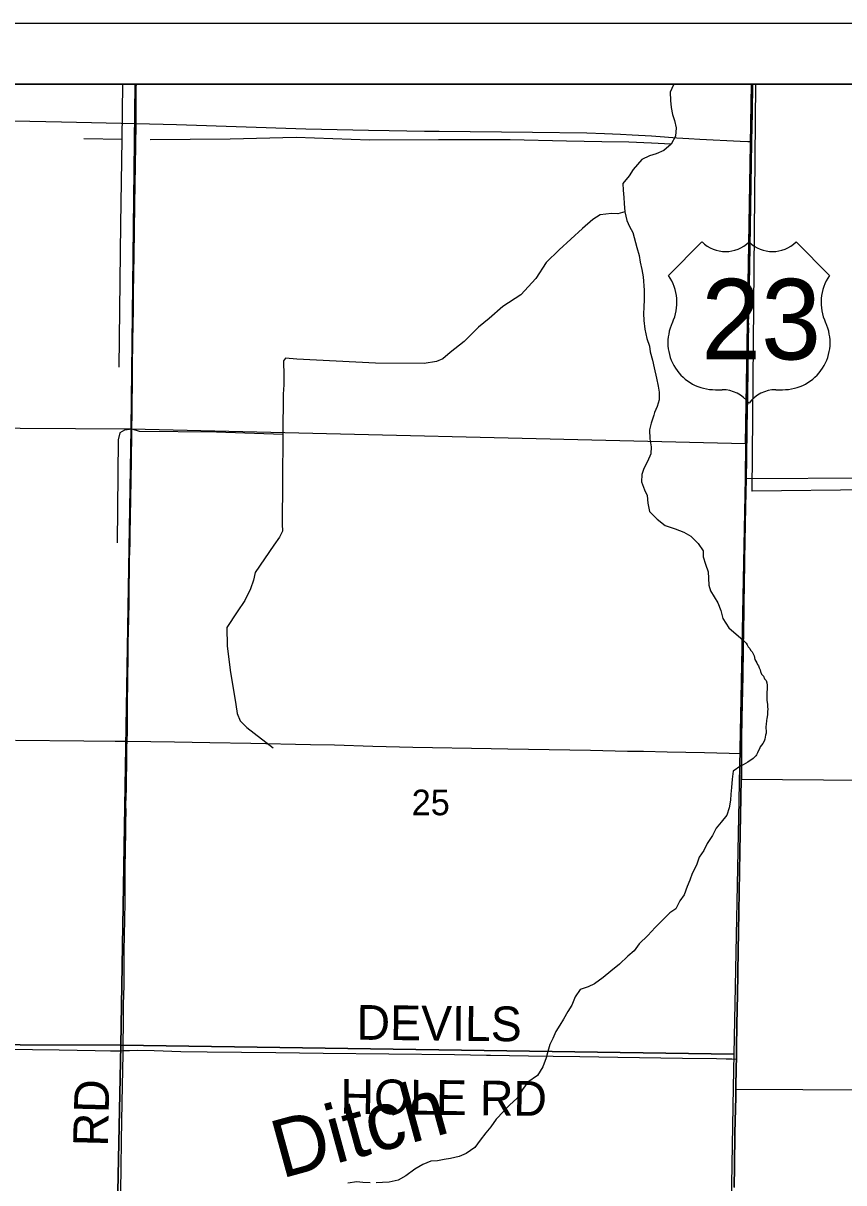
# Model space of a CAD drawing. Extents: x -8.3 to 42.1, y 0 to 22.
# Drawn here: x 6.765 to 8.107, y 19.103 to 21 of the extents above; entities that cross this region are included whole.
import ezdxf

# ---------------------------------------------------------------- set-up
doc = ezdxf.new("R2010")
doc.units = 0
for name, color, linetype in [('Default', 7, 'Continuous'), ('GM_X_Minor_River', 7, 'Continuous'), ('GM_X_Minor_River_Text', 7, 'Continuous'), ('GM_X_Section', 7, 'Continuous'), ('GM_X_Section_Text', 7, 'Continuous'), ('GM_X_State_Route', 7, 'Continuous'), ('GM_X_Township_Road', 7, 'Continuous'), ('GM_X_Township_Road_Text', 7, 'Continuous'), ('GM_X_US_Location', 7, 'Continuous'), ('GM_X_US_Route', 7, 'Continuous'), ('GM_X_US_Shield', 7, 'Continuous'), ('SH_Cut_Line', 7, 'Continuous'), ('SH_Data', 7, 'Continuous')]:
    doc.layers.add(name, color=color, linetype=linetype)

msp = doc.modelspace()

# ---------------------------------------------------------------- linework, layer by layer
at = {"layer": 'Default'}
for points in [[(6.9477, 20.9), (5.9435, 20.9), (5.9413, 20.342), (6.941, 20.3362)], [(7.9556, 20.9), (6.9477, 20.9), (6.941, 20.3362), (7.9462, 20.3122)]]:
    msp.add_lwpolyline(points, close=True, dxfattribs=at)
at = {"layer": 'GM_X_Minor_River'}
for p, q in [((7.9567, 20.2345), (7.9627, 20.9)), ((7.9566, 20.2348), (7.9567, 20.2348)), ((8.3532, 20.238), (7.9567, 20.2345))]:
    msp.add_line(p, q, dxfattribs=at)
for points in [[(6.9217, 20.4373), (6.9245, 20.6714), (6.9264, 20.8095), (6.9278, 20.9)], [(7.8289, 20.9), (7.8284, 20.8992), (7.8228, 20.8872), (7.8232, 20.8735), (7.8245, 20.8621), (7.8265, 20.8507), (7.83, 20.8407), (7.8327, 20.8289), (7.8316, 20.8152), (7.8245, 20.8021), (7.8125, 20.7918), (7.7999, 20.786), (7.7888, 20.7829), (7.7765, 20.7771), (7.7625, 20.7607), (7.7558, 20.7503), (7.7456, 20.7376), (7.7458, 20.727), (7.747, 20.7148), (7.7475, 20.7049), (7.7487, 20.6912), (7.7517, 20.6771), (7.7564, 20.6675), (7.7615, 20.6575), (7.7684, 20.6327), (7.7719, 20.6197), (7.7739, 20.609), (7.7766, 20.5972), (7.7786, 20.585), (7.7803, 20.563), (7.7803, 20.5485), (7.7796, 20.5349), (7.779, 20.525), (7.7795, 20.5133), (7.7814, 20.4992), (7.7848, 20.4843), (7.7887, 20.4717), (7.7903, 20.4622), (7.7938, 20.4484), (7.7968, 20.4358), (7.8006, 20.419), (7.8029, 20.4061), (7.8046, 20.3965), (7.8046, 20.3836), (7.8013, 20.3727), (7.7969, 20.3629)], [(6.9264, 20.8095), (6.8636, 20.811)], [(7.8245, 20.8021), (7.792, 20.8037), (7.7549, 20.8053), (7.711, 20.806), (7.6531, 20.8067), (7.5611, 20.8089), (7.4437, 20.8091), (7.3312, 20.8088), (7.2113, 20.8128), (7.1033, 20.8101), (6.9722, 20.8094)], [(7.7487, 20.6912), (7.7372, 20.6881), (7.7266, 20.6887), (7.7084, 20.6865), (7.6961, 20.6789), (7.6791, 20.6641), (7.6411, 20.6293), (7.6197, 20.6082), (7.6028, 20.5821), (7.5787, 20.5557), (7.549, 20.5367), (7.5266, 20.5168), (7.5092, 20.5024), (7.4859, 20.4794), (7.4627, 20.461), (7.4507, 20.4507), (7.4404, 20.4467), (7.4202, 20.4434), (7.3407, 20.4438), (7.2121, 20.45), (7.1936, 20.452), (7.1905, 20.4475), (7.191, 20.4228), (7.1906, 20.408), (7.1899, 20.3932), (7.1894, 20.3268), (7.1886, 20.2506), (7.1884, 20.18), (7.1885, 20.1686), (7.1837, 20.1588), (7.1743, 20.1458), (7.144, 20.101), (7.141, 20.0889), (7.1361, 20.0742), (7.127, 20.0555), (7.1144, 20.0368), (7.0978, 20.011), (7.0982, 19.981), (7.1033, 19.9414), (7.1121, 19.8854), (7.1144, 19.8702), (7.1194, 19.8583), (7.1301, 19.8474), (7.1732, 19.8145)], [(7.7969, 20.3629), (7.7961, 20.3588), (7.7916, 20.3456), (7.789, 20.3347), (7.7894, 20.3199), (7.7918, 20.3069), (7.7911, 20.2952), (7.7859, 20.2828), (7.7795, 20.2715), (7.7762, 20.2617), (7.7759, 20.2496), (7.7809, 20.2366), (7.7852, 20.227), (7.7864, 20.2144), (7.7891, 20.2011), (7.8013, 20.1883), (7.8147, 20.1781), (7.8308, 20.1724), (7.8451, 20.1671), (7.8567, 20.1604)], [(7.1894, 20.3268), (7.0808, 20.3306), (6.9547, 20.3321), (6.9427, 20.3358), (6.9301, 20.3343), (6.9228, 20.3295), (6.9199, 20.3182), (6.918, 20.1497)], [(7.8567, 20.1604), (7.8685, 20.1487), (7.8765, 20.1367), (7.877, 20.1269), (7.8805, 20.115), (7.8851, 20.1024), (7.8856, 20.0917), (7.8861, 20.0807), (7.8885, 20.0712), (7.8947, 20.0611), (7.9009, 20.0515), (7.9055, 20.0389), (7.909, 20.0259), (7.9185, 20.0109), (7.9421, 19.9902)], [(7.9421, 19.9902), (7.9473, 19.9853), (7.9487, 19.9826), (7.9506, 19.9796), (7.9528, 19.9769), (7.9543, 19.9742), (7.9569, 19.9715), (7.9587, 19.9681), (7.9602, 19.965), (7.9612, 19.9589), (7.9646, 19.9536), (7.9657, 19.9509), (7.9675, 19.9482), (7.9686, 19.9452), (7.9701, 19.9421), (7.9704, 19.9391), (7.9719, 19.9349), (7.9752, 19.9318), (7.977, 19.9272), (7.9797, 19.9246), (7.9807, 19.9204), (7.9814, 19.9169), (7.9813, 19.9097), (7.9809, 19.9059), (7.9808, 19.898), (7.9811, 19.8953), (7.9811, 19.8915), (7.9821, 19.8858), (7.982, 19.8809), (7.9824, 19.8779), (7.9819, 19.8733), (7.9818, 19.8684), (7.981, 19.8623), (7.9802, 19.8589), (7.9797, 19.8525), (7.9793, 19.8494), (7.9792, 19.8468), (7.9799, 19.8418), (7.9799, 19.8384), (7.9787, 19.835), (7.9783, 19.832), (7.9778, 19.8282), (7.9767, 19.8252), (7.9743, 19.8214), (7.972, 19.8188), (7.9701, 19.8158), (7.9689, 19.8128), (7.9666, 19.809), (7.9654, 19.806), (7.9639, 19.8031), (7.9629, 19.8011)], [(7.9629, 19.8011), (7.9586, 19.797), (7.9497, 19.7908), (7.942, 19.7864), (7.9383, 19.785)], [(7.9383, 19.785), (7.9257, 19.776), (7.924, 19.7629), (7.9233, 19.7496), (7.9219, 19.7387), (7.9217, 19.7288), (7.9195, 19.716), (7.9154, 19.7039), (7.9064, 19.6924), (7.8982, 19.6827), (7.8922, 19.6711), (7.8832, 19.658), (7.8776, 19.6464), (7.8701, 19.6356), (7.866, 19.6224), (7.8585, 19.6085), (7.8548, 19.598), (7.8508, 19.5875), (7.8455, 19.5736), (7.8388, 19.5639), (7.8321, 19.5511), (7.8224, 19.5445), (7.8092, 19.5312), (7.798, 19.5201), (7.7863, 19.5074), (7.7723, 19.4937), (7.7637, 19.4822), (7.7533, 19.4733), (7.7397, 19.4604), (7.7258, 19.4486), (7.7134, 19.4386), (7.6991, 19.4283), (7.6884, 19.4233), (7.6754, 19.4191), (7.6675, 19.4067), (7.6619, 19.3932), (7.6556, 19.3831), (7.6485, 19.3704), (7.6425, 19.3603), (7.6358, 19.3502), (7.6306, 19.3385), (7.6262, 19.3288), (7.6225, 19.3175), (7.62, 19.3073), (7.6147, 19.2923), (7.606, 19.2784), (7.5902, 19.2674), (7.5812, 19.2551), (7.5725, 19.2413), (7.5597, 19.2295), (7.55, 19.2194), (7.538, 19.2068), (7.5297, 19.1941), (7.5215, 19.1845), (7.5121, 19.1722), (7.5035, 19.1602), (7.4892, 19.1503), (7.4774, 19.1457), (7.4633, 19.1422), (7.453, 19.1406), (7.442, 19.1386), (7.4314, 19.1377), (7.4184, 19.1327), (7.4049, 19.1251), (7.3902, 19.114), (7.3776, 19.1071), (7.3631, 19.1037), (7.3525, 19.1028), (7.3419, 19.1023)], [(7.332, 19.1025), (7.3203, 19.1032), (7.3101, 19.1042), (7.2953, 19.1019)]]:
    msp.add_lwpolyline(points, dxfattribs=at)
at = {"layer": 'GM_X_Section'}
for points in [[(6.941, 20.3362), (6.9241, 19.3275), (5.9346, 19.331), (5.9413, 20.342)], [(7.9462, 20.3122), (7.9454, 20.2554), (7.9268, 19.313), (6.9241, 19.3275), (6.941, 20.3362)], [(6.9241, 19.3275), (6.9034, 18.3155), (6.8731, 18.3158), (5.9121, 18.3219), (5.9346, 19.331)], [(7.9268, 19.313), (7.9258, 19.2592), (7.9095, 18.3054), (6.9034, 18.3155), (6.9241, 19.3275)]]:
    msp.add_lwpolyline(points, close=True, dxfattribs=at)
at = {"layer": 'GM_X_State_Route'}
for points in [[(6.7517, 19.8266), (6.8635, 19.8255), (6.9151, 19.8253), (6.9345, 19.8251), (7.012, 19.8242), (7.0698, 19.8231), (7.1369, 19.8217), (7.2345, 19.8195), (7.2736, 19.819), (7.3364, 19.8168), (7.4021, 19.8152), (7.5301, 19.8131), (7.5574, 19.8125), (7.6922, 19.8103), (7.7528, 19.8089), (7.7789, 19.8086), (7.8181, 19.8077), (7.879, 19.8065), (7.9397, 19.8051)], [(7.9397, 19.8051), (7.9395, 19.7885), (7.9394, 19.7756), (7.9393, 19.763)], [(7.9393, 19.763), (8.1406, 19.7613), (8.3709, 19.76), (8.5318, 19.7588), (8.7592, 19.7563), (8.8612, 19.7549), (8.8908, 19.7552), (8.9, 19.7557)]]:
    msp.add_lwpolyline(points, dxfattribs=at)
at = {"layer": 'GM_X_Township_Road'}
for p, q in [((7.9473, 20.2551), (8.8918, 20.2586)), ((7.9303, 19.2556), (8.9, 19.2515))]:
    msp.add_line(p, q, dxfattribs=at)
for points in [[(7.9276, 19.0953), (7.928, 19.1295), (7.9288, 19.1839), (7.9299, 19.243), (7.9301, 19.2561), (7.9307, 19.2927), (7.931, 19.3055), (7.9315, 19.3254), (7.932, 19.3596), (7.9325, 19.3891), (7.9327, 19.4077), (7.9334, 19.4466), (7.9338, 19.4823), (7.9345, 19.5134), (7.9366, 19.644), (7.939, 19.7636), (7.9392, 19.7761), (7.9393, 19.789), (7.9394, 19.8056), (7.9397, 19.8294), (7.9401, 19.8635), (7.9414, 19.9318), (7.9421, 19.9769), (7.9433, 20.0375), (7.9434, 20.0562), (7.9436, 20.0748), (7.9445, 20.1229), (7.946, 20.2084), (7.947, 20.255), (7.947, 20.2556), (7.9476, 20.2861), (7.9484, 20.3389), (7.9491, 20.3871), (7.9499, 20.4384), (7.9506, 20.471), (7.9505, 20.485), (7.9507, 20.5005), (7.9506, 20.5036), (7.9507, 20.5083), (7.9506, 20.5114), (7.9507, 20.5191), (7.9519, 20.572), (7.9532, 20.6341), (7.9541, 20.7009), (7.9558, 20.805), (7.9559, 20.8068), (7.9567, 20.8532), (7.9572, 20.9), (3.9382, 20.9)], [(6.9491, 20.836), (6.9496, 20.8951), (6.9497, 20.9)], [(8.9, 20.9), (7.9572, 20.9), (7.9567, 20.8532), (7.9559, 20.8068), (7.9558, 20.805), (7.9541, 20.7009), (7.9532, 20.6341), (7.9519, 20.572), (7.9507, 20.5191), (7.9506, 20.5114), (7.9507, 20.5083), (7.9506, 20.5036), (7.9507, 20.5005), (7.9505, 20.485), (7.9506, 20.471), (7.9499, 20.4384), (7.9491, 20.3871), (7.9484, 20.3389), (7.9476, 20.2861), (7.947, 20.2556), (7.947, 20.255), (7.946, 20.2084), (7.9445, 20.1229), (7.9436, 20.0748), (7.9434, 20.0562), (7.9433, 20.0375), (7.9421, 19.9769), (7.9414, 19.9318), (7.9401, 19.8635), (7.9397, 19.8294), (7.9394, 19.8056), (7.9393, 19.789), (7.9392, 19.7761), (7.939, 19.7636), (7.9366, 19.644), (7.9345, 19.5134), (7.9338, 19.4823), (7.9334, 19.4466), (7.9327, 19.4077), (7.9325, 19.3891), (7.932, 19.3596), (7.9315, 19.3254), (7.931, 19.3055), (7.9307, 19.2927), (7.9301, 19.2561), (7.9299, 19.243), (7.9288, 19.1839), (7.928, 19.1295), (7.9276, 19.0953)], [(5.9435, 20.847), (5.9532, 20.8469), (6.0414, 20.846), (6.0713, 20.8459), (6.1229, 20.8452), (6.1607, 20.8445), (6.2279, 20.8437), (6.2695, 20.8434), (6.2979, 20.8433), (6.3563, 20.8427), (6.4371, 20.8419), (6.5254, 20.8411), (6.5665, 20.8407), (6.615, 20.8405), (6.6604, 20.8406), (6.7499, 20.84), (6.827, 20.8388), (6.9491, 20.836)], [(6.9345, 19.8251), (6.935, 19.8405), (6.9349, 19.8504), (6.935, 19.8769), (6.9352, 19.8859), (6.9353, 19.8929), (6.9356, 19.9167), (6.9362, 19.9744), (6.9364, 19.9879), (6.9367, 20.0028), (6.9378, 20.051), (6.9378, 20.0676), (6.938, 20.0808), (6.9383, 20.1011), (6.9387, 20.1222), (6.9395, 20.1495), (6.9396, 20.1655), (6.9399, 20.1909), (6.9404, 20.2239), (6.941, 20.25), (6.9415, 20.2873), (6.9421, 20.3265), (6.9431, 20.416), (6.9433, 20.4359), (6.9436, 20.4533), (6.9437, 20.4632), (6.9439, 20.4806), (6.9448, 20.5309), (6.9452, 20.5582), (6.9462, 20.621), (6.9468, 20.6589), (6.9474, 20.7043), (6.9482, 20.7671), (6.9491, 20.8342), (6.9491, 20.836)], [(6.9491, 20.836), (7.0154, 20.8344), (7.2271, 20.8274), (7.3295, 20.825), (7.3631, 20.8245), (7.4209, 20.8234), (7.4452, 20.8232), (7.5975, 20.8215), (7.6864, 20.8204), (7.7155, 20.8195), (7.7413, 20.8184), (7.7606, 20.8172), (7.7922, 20.8155), (7.8133, 20.8142), (7.8337, 20.8126), (7.8535, 20.8115), (7.8715, 20.8105), (7.9374, 20.807), (7.9498, 20.8065), (7.9561, 20.8062)], [(6.928, 19.3188), (6.9286, 19.3741), (6.9288, 19.3943), (6.9295, 19.4254), (6.9295, 19.4471), (6.9299, 19.4813), (6.9303, 19.5077), (6.9308, 19.5326), (6.9311, 19.5621), (6.9314, 19.6041), (6.9315, 19.6243), (6.9318, 19.6397), (6.9319, 19.6555), (6.9322, 19.669), (6.9326, 19.6938), (6.9329, 19.7095), (6.9327, 19.7218), (6.9333, 19.7471), (6.9337, 19.7657), (6.934, 19.7845), (6.9342, 19.7998), (6.9341, 19.816), (6.9345, 19.8251)], [(5.9308, 19.3255), (5.9468, 19.3255), (5.9841, 19.3255), (6.0183, 19.3255), (6.1116, 19.3256), (6.1613, 19.3256), (6.2266, 19.3251), (6.2887, 19.3249), (6.3385, 19.3252), (6.3727, 19.3249), (6.4131, 19.3244), (6.4939, 19.3236), (6.5436, 19.3229), (6.6058, 19.3224), (6.6586, 19.322), (6.727, 19.3212), (6.7798, 19.3207), (6.8234, 19.3201), (6.8824, 19.3189), (6.9073, 19.3184), (6.9227, 19.3185), (6.928, 19.3188)], [(6.919, 18.8131), (6.9192, 18.8299), (6.9198, 18.8657), (6.9206, 18.9061), (6.922, 18.9745), (6.9231, 19.0103), (6.9238, 19.0647), (6.9243, 19.0911), (6.9245, 19.102), (6.9246, 19.1144), (6.925, 19.1424), (6.9251, 19.1564), (6.9253, 19.172), (6.9259, 19.2031), (6.9265, 19.2342), (6.927, 19.2606), (6.928, 19.3134), (6.928, 19.3188)], [(6.928, 19.3188), (6.932, 19.3191), (6.9383, 19.3193), (6.9507, 19.3194), (6.9787, 19.3188), (7.0222, 19.3176), (7.0657, 19.3169), (7.1216, 19.3162), (7.1776, 19.3156), (7.2553, 19.3145), (7.4698, 19.3124), (7.5226, 19.3116), (7.5288, 19.3115), (7.591, 19.3104), (7.6314, 19.3097), (7.6749, 19.3092), (7.737, 19.3083), (7.8427, 19.3065), (7.8987, 19.3057), (7.9142, 19.3055), (7.9235, 19.3052), (7.9312, 19.3049)]]:
    msp.add_lwpolyline(points, dxfattribs=at)
at = {"layer": 'GM_X_US_Route'}
for points in [[(7.9397, 19.8051), (7.9399, 19.8288), (7.9403, 19.8629), (7.9416, 19.9313), (7.9424, 19.9763), (7.9435, 20.0369), (7.9436, 20.0556), (7.9438, 20.0742), (7.9448, 20.1224), (7.9462, 20.2078), (7.9472, 20.2544), (7.9473, 20.2551), (7.9478, 20.2855), (7.9486, 20.3384), (7.9493, 20.3865), (7.9501, 20.4378), (7.9508, 20.4704), (7.9507, 20.4844), (7.9509, 20.5), (7.9508, 20.5031), (7.9509, 20.5077), (7.9508, 20.5108), (7.9509, 20.5186), (7.9521, 20.5714), (7.9534, 20.6336), (7.9543, 20.7004), (7.9561, 20.8045), (7.9561, 20.8062), (7.9569, 20.8527), (7.9575, 20.9)], [(7.9393, 19.763), (7.9394, 19.7756), (7.9395, 19.7885), (7.9397, 19.8051)], [(7.9278, 19.0948), (7.9282, 19.129), (7.929, 19.1834), (7.9301, 19.2424), (7.9303, 19.2556), (7.931, 19.2922), (7.9312, 19.3049), (7.9317, 19.3248), (7.9322, 19.359), (7.9327, 19.3885), (7.9329, 19.4072), (7.9336, 19.446), (7.934, 19.4818), (7.9348, 19.5129), (7.9368, 19.6434), (7.9393, 19.763)]]:
    msp.add_lwpolyline(points, dxfattribs=at)
at = {"layer": 'GM_X_US_Shield'}
for p, q in [((7.8748, 20.642), (7.8199, 20.5871)), ((8.0835, 20.5871), (8.0286, 20.642)), ((7.8968, 20.4003), (7.9078, 20.4003)), ((7.9957, 20.4003), (8.0066, 20.4003))]:
    msp.add_line(p, q, dxfattribs=at)
for centre, radius, start, end in [((7.9133, 20.6812), 0.0549, 225.573, 314.427), ((7.9902, 20.6812), 0.0549, 225.573, 314.427), ((7.7569, 20.543), 0.0769, 334.5471, 35.0009), ((8.1465, 20.543), 0.0769, 144.9991, 205.4529), ((7.8959, 20.4772), 0.0769, 154.8319, 270.6383), ((8.0075, 20.4772), 0.0769, 269.3617, 25.1681), ((7.9078, 20.3454), 0.0549, 36.8699, 90), ((7.9957, 20.3454), 0.0549, 90, 143.1301)]:
    msp.add_arc(centre, radius, start, end, dxfattribs=at)
at = {"layer": 'SH_Cut_Line'}
for points in [[(7.9276, 19.0953), (7.928, 19.1295), (7.9288, 19.1839), (7.9299, 19.243), (7.9301, 19.2561), (7.9307, 19.2927), (7.931, 19.3055), (7.9315, 19.3254), (7.932, 19.3596), (7.9325, 19.3891), (7.9327, 19.4077), (7.9334, 19.4466), (7.9338, 19.4823), (7.9345, 19.5134), (7.9366, 19.644), (7.939, 19.7636), (7.9392, 19.7761), (7.9393, 19.789), (7.9394, 19.8056), (7.9397, 19.8294), (7.9401, 19.8635), (7.9414, 19.9318), (7.9421, 19.9769), (7.9433, 20.0375), (7.9434, 20.0562), (7.9436, 20.0748), (7.9445, 20.1229), (7.946, 20.2084), (7.947, 20.255), (7.947, 20.2556), (7.9476, 20.2861), (7.9484, 20.3389), (7.9491, 20.3871), (7.9499, 20.4384), (7.9506, 20.471), (7.9505, 20.485), (7.9507, 20.5005), (7.9506, 20.5036), (7.9507, 20.5083), (7.9506, 20.5114), (7.9507, 20.5191), (7.9519, 20.572), (7.9532, 20.6341), (7.9541, 20.7009), (7.9558, 20.805), (7.9559, 20.8068), (7.9567, 20.8532), (7.9572, 20.9), (2.1, 20.9)], [(8.9, 20.9), (7.9572, 20.9), (7.9567, 20.8532), (7.9559, 20.8068), (7.9558, 20.805), (7.9541, 20.7009), (7.9532, 20.6341), (7.9519, 20.572), (7.9507, 20.5191), (7.9506, 20.5114), (7.9507, 20.5083), (7.9506, 20.5036), (7.9507, 20.5005), (7.9505, 20.485), (7.9506, 20.471), (7.9499, 20.4384), (7.9491, 20.3871), (7.9484, 20.3389), (7.9476, 20.2861), (7.947, 20.2556), (7.947, 20.255), (7.946, 20.2084), (7.9445, 20.1229), (7.9436, 20.0748), (7.9434, 20.0562), (7.9433, 20.0375), (7.9421, 19.9769), (7.9414, 19.9318), (7.9401, 19.8635), (7.9397, 19.8294), (7.9394, 19.8056), (7.9393, 19.789), (7.9392, 19.7761), (7.939, 19.7636), (7.9366, 19.644), (7.9345, 19.5134), (7.9338, 19.4823), (7.9334, 19.4466), (7.9327, 19.4077), (7.9325, 19.3891), (7.932, 19.3596), (7.9315, 19.3254), (7.931, 19.3055), (7.9307, 19.2927), (7.9301, 19.2561), (7.9299, 19.243), (7.9288, 19.1839), (7.928, 19.1295), (7.9276, 19.0953)]]:
    msp.add_lwpolyline(points, dxfattribs=at)
at = {"layer": 'SH_Data'}
for p, q in [((2, 21), (9, 21)), ((2.1, 20.9), (8.9, 20.9))]:
    msp.add_line(p, q, dxfattribs=at)

# ---------------------------------------------------------------- texts
at = {"layer": 'GM_X_Minor_River_Text'}
msp.add_text('Ditch', height=0.09475, rotation=15.3113, dxfattribs=at).set_placement((7.1868, 19.1092))
at = {"layer": 'GM_X_Section_Text'}
msp.add_text('25', height=0.04186, rotation=0, dxfattribs=at).set_placement((7.4, 19.704))
at = {"layer": 'GM_X_Township_Road_Text'}
for s, rotation, p in [('DEVILS', 359.4218, (7.3095, 19.3367)), ('RD', 88.5292, (6.9029, 19.1614)), ('HOLE RD', 359.3614, (7.2832, 19.2156))]:
    msp.add_text(s, height=0.05682, rotation=rotation, dxfattribs=at).set_placement(p)
at = {"layer": 'GM_X_US_Location'}
for s, p in [('0', (7.9516, 20.5146)), ('/', (7.9517, 20.5146))]:
    msp.add_text(s, height=0.000189, dxfattribs=at).set_placement(p)
msp.add_text('23', height=0.000189, rotation=0, dxfattribs=at).set_placement((7.9125, 20.4754))
at = {"layer": 'GM_X_US_Shield'}
msp.add_text('23', height=0.13184, dxfattribs=at).set_placement((7.8734, 20.4498))

doc.saveas('drawing.dxf')
